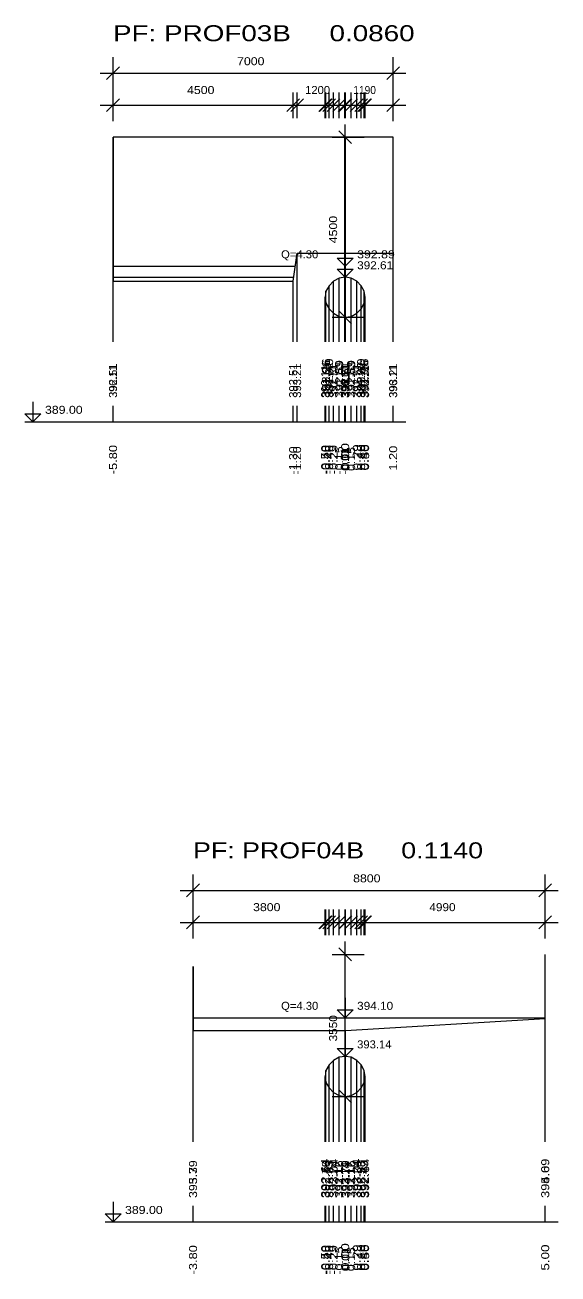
# Model space of a CAD drawing. Extents: x 7 to 442, y -393 to 441.
# Drawn here: x 414.04 to 427.36, y 175.67 to 206.88 of the extents above; entities that cross this region are included whole.
import ezdxf

# ---------------------------------------------------------------- set-up
doc = ezdxf.new("R2010")
doc.units = 0
doc.header["$LTSCALE"] = 0.08
doc.layers.add('7', color=7, linetype='Continuous', lineweight=13)

msp = doc.modelspace()

# ---------------------------------------------------------------- linework, layer by layer
at = {"layer": '7'}
for p, q in [((416.238, 204.479), (416.238, 206.079)), ((423.238, 204.479), (423.238, 206.079)), ((416.078, 205.519), (416.398, 205.839)), ((423.078, 205.519), (423.398, 205.839)), ((415.918, 205.679), (423.558, 205.679)), ((416.238, 204.559), (416.238, 205.199)), ((416.238, 204.559), (416.238, 205.199)), ((420.738, 204.559), (420.738, 205.199)), ((420.838, 204.559), (420.838, 205.199)), ((421.538, 204.559), (421.538, 205.199)), ((421.558, 204.559), (421.558, 205.199)), ((421.558, 204.559), (421.558, 205.199)), ((421.638, 204.559), (421.638, 205.199)), ((421.638, 204.559), (421.638, 205.199)), ((421.748, 204.559), (421.748, 205.199)), ((421.748, 204.559), (421.748, 205.199)), ((421.888, 204.559), (421.888, 205.199)), ((421.888, 204.559), (421.888, 205.199)), ((422.028, 204.559), (422.028, 205.199)), ((422.038, 204.559), (422.038, 205.199)), ((422.038, 204.559), (422.038, 205.199)), ((422.038, 204.559), (422.038, 205.199)), ((422.048, 204.559), (422.048, 205.199)), ((422.048, 204.559), (422.048, 205.199)), ((422.048, 204.559), (422.048, 205.199)), ((422.188, 204.559), (422.188, 205.199)), ((422.188, 204.559), (422.188, 205.199)), ((422.328, 204.559), (422.328, 205.199)), ((422.328, 204.559), (422.328, 205.199)), ((422.438, 204.559), (422.438, 205.199)), ((422.438, 204.559), (422.438, 205.199)), ((422.518, 204.559), (422.518, 205.199)), ((422.518, 204.559), (422.518, 205.199)), ((422.538, 204.559), (422.538, 205.199)), ((423.238, 204.559), (423.238, 205.199)), ((423.238, 204.559), (423.238, 205.199)), ((415.918, 204.879), (423.558, 204.879)), ((416.078, 204.719), (416.398, 205.039)), ((416.078, 204.719), (416.398, 205.039)), ((420.578, 204.719), (420.898, 205.039)), ((420.678, 204.719), (420.998, 205.039)), ((421.378, 204.719), (421.698, 205.039)), ((421.398, 204.719), (421.718, 205.039)), ((421.398, 204.719), (421.718, 205.039)), ((421.478, 204.719), (421.798, 205.039)), ((421.478, 204.719), (421.798, 205.039)), ((421.588, 204.719), (421.908, 205.039)), ((421.588, 204.719), (421.908, 205.039)), ((421.728, 204.719), (422.048, 205.039)), ((421.728, 204.719), (422.048, 205.039)), ((421.868, 204.719), (422.188, 205.039)), ((421.878, 204.719), (422.198, 205.039)), ((421.878, 204.719), (422.198, 205.039)), ((421.878, 204.719), (422.198, 205.039)), ((421.888, 204.719), (422.208, 205.039)), ((421.888, 204.719), (422.208, 205.039)), ((421.888, 204.719), (422.208, 205.039)), ((422.028, 204.719), (422.348, 205.039)), ((422.028, 204.719), (422.348, 205.039)), ((422.168, 204.719), (422.488, 205.039)), ((422.168, 204.719), (422.488, 205.039)), ((422.278, 204.719), (422.598, 205.039)), ((422.278, 204.719), (422.598, 205.039)), ((422.358, 204.719), (422.678, 205.039)), ((422.358, 204.719), (422.678, 205.039)), ((422.378, 204.719), (422.698, 205.039)), ((423.078, 204.719), (423.398, 205.039)), ((423.078, 204.719), (423.398, 205.039)), ((422.198, 203.919), (421.878, 204.239)), ((422.038, 199.419), (422.038, 204.399)), ((416.238, 198.966), (416.238, 204.079)), ((421.718, 204.079), (422.518, 204.079)), ((422.028, 198.966), (422.028, 204.079)), ((422.048, 198.966), (422.048, 204.079)), ((423.238, 198.966), (423.238, 204.079)), ((420.838, 198.966), (420.838, 201.179)), ((422.038, 198.966), (422.038, 201.179)), ((422.048, 198.966), (422.048, 201.179)), ((423.238, 198.966), (423.238, 201.179)), ((416.238, 200.853), (420.791, 200.853)), ((416.238, 200.579), (420.752, 200.579)), ((416.238, 198.966), (416.238, 200.479)), ((420.738, 198.966), (420.738, 200.479)), ((421.748, 198.966), (421.748, 200.479)), ((421.888, 198.966), (421.888, 200.559)), ((422.038, 198.966), (422.038, 200.579)), ((422.048, 198.966), (422.048, 200.579)), ((422.188, 198.966), (422.188, 200.559)), ((422.328, 198.966), (422.328, 200.479)), ((421.558, 198.966), (421.558, 200.229)), ((421.638, 198.966), (421.638, 200.369)), ((422.438, 198.966), (422.438, 200.369)), ((422.518, 198.966), (422.518, 200.229)), ((421.538, 198.966), (421.538, 200.079)), ((421.558, 198.966), (421.558, 199.929)), ((422.518, 198.966), (422.518, 199.929)), ((422.538, 198.966), (422.538, 200.079)), ((421.638, 198.966), (421.638, 199.789)), ((421.718, 199.579), (422.518, 199.579)), ((421.748, 198.966), (421.748, 199.679)), ((422.198, 199.419), (421.878, 199.739)), ((421.888, 198.966), (421.888, 199.599)), ((422.038, 198.966), (422.038, 199.579)), ((422.188, 198.966), (422.188, 199.599)), ((422.328, 198.966), (422.328, 199.679)), ((422.438, 198.966), (422.438, 199.789)), ((416.238, 196.966), (416.238, 197.366)), ((416.238, 196.966), (416.238, 197.366)), ((420.738, 196.966), (420.738, 197.366)), ((420.838, 196.966), (420.838, 197.366)), ((421.538, 196.966), (421.538, 197.366)), ((421.558, 196.966), (421.558, 197.366)), ((421.558, 196.966), (421.558, 197.366)), ((421.638, 196.966), (421.638, 197.366)), ((421.638, 196.966), (421.638, 197.366)), ((421.748, 196.966), (421.748, 197.366)), ((421.748, 196.966), (421.748, 197.366)), ((421.888, 196.966), (421.888, 197.366)), ((421.888, 196.966), (421.888, 197.366)), ((422.028, 196.966), (422.028, 197.366)), ((422.038, 196.966), (422.038, 197.366)), ((422.038, 196.966), (422.038, 197.366)), ((422.038, 196.966), (422.038, 197.366)), ((422.048, 196.966), (422.048, 197.366)), ((422.048, 196.966), (422.048, 197.366)), ((422.048, 196.966), (422.048, 197.366)), ((422.188, 196.966), (422.188, 197.366)), ((422.188, 196.966), (422.188, 197.366)), ((422.328, 196.966), (422.328, 197.366)), ((422.328, 196.966), (422.328, 197.366)), ((422.438, 196.966), (422.438, 197.366)), ((422.438, 196.966), (422.438, 197.366)), ((422.518, 196.966), (422.518, 197.366)), ((422.518, 196.966), (422.518, 197.366)), ((422.538, 196.966), (422.538, 197.366)), ((423.238, 196.966), (423.238, 197.366)), ((423.238, 196.966), (423.238, 197.366)), ((414.038, 196.966), (423.558, 196.966)), ((418.238, 184.055), (418.238, 185.655)), ((427.038, 184.055), (427.038, 185.655)), ((417.918, 185.255), (427.358, 185.255)), ((418.078, 185.095), (418.398, 185.415)), ((426.878, 185.095), (427.198, 185.415)), ((418.078, 184.295), (418.398, 184.615)), ((418.078, 184.295), (418.398, 184.615)), ((418.238, 184.135), (418.238, 184.775)), ((418.238, 184.135), (418.238, 184.775)), ((421.378, 184.295), (421.698, 184.615)), ((421.398, 184.295), (421.718, 184.615)), ((421.398, 184.295), (421.718, 184.615)), ((421.478, 184.295), (421.798, 184.615)), ((421.478, 184.295), (421.798, 184.615)), ((421.538, 184.135), (421.538, 184.775)), ((421.558, 184.135), (421.558, 184.775)), ((421.558, 184.135), (421.558, 184.775)), ((421.588, 184.295), (421.908, 184.615)), ((421.588, 184.295), (421.908, 184.615)), ((421.638, 184.135), (421.638, 184.775)), ((421.638, 184.135), (421.638, 184.775)), ((421.728, 184.295), (422.048, 184.615)), ((421.728, 184.295), (422.048, 184.615)), ((421.748, 184.135), (421.748, 184.775)), ((421.748, 184.135), (421.748, 184.775)), ((421.878, 184.295), (422.198, 184.615)), ((421.878, 184.295), (422.198, 184.615)), ((421.878, 184.295), (422.198, 184.615)), ((421.888, 184.135), (421.888, 184.775)), ((421.888, 184.135), (421.888, 184.775)), ((421.888, 184.295), (422.208, 184.615)), ((421.888, 184.295), (422.208, 184.615)), ((422.028, 184.295), (422.348, 184.615)), ((422.028, 184.295), (422.348, 184.615)), ((422.038, 184.135), (422.038, 184.775)), ((422.038, 184.135), (422.038, 184.775)), ((422.038, 184.135), (422.038, 184.775)), ((422.048, 184.135), (422.048, 184.775)), ((422.048, 184.135), (422.048, 184.775)), ((422.168, 184.295), (422.488, 184.615)), ((422.168, 184.295), (422.488, 184.615)), ((422.188, 184.135), (422.188, 184.775)), ((422.188, 184.135), (422.188, 184.775)), ((422.278, 184.295), (422.598, 184.615)), ((422.278, 184.295), (422.598, 184.615)), ((422.328, 184.135), (422.328, 184.775)), ((422.328, 184.135), (422.328, 184.775)), ((422.358, 184.295), (422.678, 184.615)), ((422.358, 184.295), (422.678, 184.615)), ((422.378, 184.295), (422.698, 184.615)), ((422.438, 184.135), (422.438, 184.775)), ((422.438, 184.135), (422.438, 184.775)), ((422.518, 184.135), (422.518, 184.775)), ((422.518, 184.135), (422.518, 184.775)), ((422.538, 184.135), (422.538, 184.775)), ((426.878, 184.295), (427.198, 184.615)), ((426.878, 184.295), (427.198, 184.615)), ((427.038, 184.135), (427.038, 184.775)), ((427.038, 184.135), (427.038, 184.775)), ((417.918, 184.455), (427.358, 184.455)), ((422.038, 179.945), (422.038, 183.975)), ((421.718, 183.655), (422.518, 183.655)), ((422.198, 183.495), (421.878, 183.815)), ((427.038, 178.966), (427.038, 183.655)), ((418.238, 178.966), (418.238, 183.355)), ((418.238, 182.069), (427.038, 182.069)), ((427.038, 178.966), (427.038, 182.055)), ((418.238, 178.966), (418.238, 181.755)), ((422.038, 178.966), (422.038, 181.755)), ((422.048, 178.966), (422.048, 181.755)), ((421.888, 178.966), (421.888, 181.085)), ((422.038, 178.966), (422.038, 181.105)), ((422.038, 181.105), (422.048, 181.105)), ((422.048, 178.966), (422.048, 181.105)), ((422.188, 178.966), (422.188, 181.085)), ((421.638, 178.966), (421.638, 180.895)), ((421.748, 178.966), (421.748, 181.005)), ((422.328, 178.966), (422.328, 181.005)), ((422.438, 178.966), (422.438, 180.895)), ((421.538, 178.966), (421.538, 180.605)), ((421.558, 178.966), (421.558, 180.755)), ((421.558, 178.966), (421.558, 180.455)), ((422.518, 178.966), (422.518, 180.755)), ((422.518, 178.966), (422.518, 180.455)), ((422.538, 178.966), (422.538, 180.605)), ((421.638, 178.966), (421.638, 180.315)), ((421.748, 178.966), (421.748, 180.205)), ((422.198, 179.945), (421.878, 180.265)), ((422.328, 178.966), (422.328, 180.205)), ((422.438, 178.966), (422.438, 180.315)), ((421.718, 180.105), (422.518, 180.105)), ((421.888, 178.966), (421.888, 180.125)), ((422.038, 178.966), (422.038, 180.105)), ((422.188, 178.966), (422.188, 180.125)), ((418.238, 176.966), (418.238, 177.366)), ((418.238, 176.966), (418.238, 177.366)), ((421.538, 176.966), (421.538, 177.366)), ((421.558, 176.966), (421.558, 177.366)), ((421.558, 176.966), (421.558, 177.366)), ((421.638, 176.966), (421.638, 177.366)), ((421.638, 176.966), (421.638, 177.366)), ((421.748, 176.966), (421.748, 177.366)), ((421.748, 176.966), (421.748, 177.366)), ((421.888, 176.966), (421.888, 177.366)), ((421.888, 176.966), (421.888, 177.366)), ((422.038, 176.966), (422.038, 177.366)), ((422.038, 176.966), (422.038, 177.366)), ((422.038, 176.966), (422.038, 177.366)), ((422.048, 176.966), (422.048, 177.366)), ((422.048, 176.966), (422.048, 177.366)), ((422.188, 176.966), (422.188, 177.366)), ((422.188, 176.966), (422.188, 177.366)), ((422.328, 176.966), (422.328, 177.366)), ((422.328, 176.966), (422.328, 177.366)), ((422.438, 176.966), (422.438, 177.366)), ((422.438, 176.966), (422.438, 177.366)), ((422.518, 176.966), (422.518, 177.366)), ((422.518, 176.966), (422.518, 177.366)), ((422.538, 176.966), (422.538, 177.366)), ((427.038, 176.966), (427.038, 177.366)), ((427.038, 176.966), (427.038, 177.366)), ((416.038, 176.966), (427.358, 176.966))]:
    msp.add_line(p, q, dxfattribs=at)
for points in [[(422.028, 204.079), (416.238, 204.079), (416.238, 200.479), (420.738, 200.479), (420.838, 201.179), (422.038, 201.179), (422.038, 200.579), (421.888, 200.559), (421.748, 200.479), (421.638, 200.369), (421.558, 200.229), (421.538, 200.079), (421.558, 199.929), (421.638, 199.789), (421.748, 199.679), (421.888, 199.599), (422.038, 199.579), (422.188, 199.599), (422.328, 199.679), (422.438, 199.789), (422.518, 199.929), (422.538, 200.079), (422.518, 200.229), (422.438, 200.369), (422.328, 200.479), (422.188, 200.559), (422.048, 200.579), (422.048, 201.179), (423.238, 201.179), (423.238, 204.079), (422.048, 204.079)], [(422.038, 201.353), (422.038, 200.853), (421.838, 201.053), (422.238, 201.053), (422.038, 200.853), (422.048, 200.853)], [(422.038, 201.079), (422.038, 200.579), (421.838, 200.779), (422.238, 200.779), (422.038, 200.579), (422.048, 200.579)], [(414.238, 197.466), (414.238, 196.966), (414.038, 197.166), (414.438, 197.166), (414.238, 196.966)], [(418.238, 183.355), (418.238, 181.755), (422.038, 181.755), (422.038, 181.105), (421.888, 181.085), (421.748, 181.005), (421.638, 180.895), (421.558, 180.755), (421.538, 180.605), (421.558, 180.455), (421.638, 180.315), (421.748, 180.205), (421.888, 180.125), (422.038, 180.105), (422.188, 180.125), (422.328, 180.205), (422.438, 180.315), (422.518, 180.455), (422.538, 180.605), (422.518, 180.755), (422.438, 180.895), (422.328, 181.005), (422.188, 181.085), (422.048, 181.105), (422.048, 181.755), (427.038, 182.055), (427.038, 183.655)], [(422.038, 182.569), (422.038, 182.069), (421.838, 182.269), (422.238, 182.269), (422.038, 182.069)], [(422.038, 181.605), (422.038, 181.105), (421.838, 181.305), (422.238, 181.305), (422.038, 181.105)], [(416.238, 177.466), (416.238, 176.966), (416.038, 177.166), (416.438, 177.166), (416.238, 176.966)]]:
    msp.add_lwpolyline(points, dxfattribs=at)

# ---------------------------------------------------------------- texts
for s, height, width, p in [('PF: PROF03B     0.0860', 0.4, 1.3, (416.238, 206.479)), ('7000', 0.2, 1.15, (419.338, 205.879)), ('4500', 0.2, 1.15, (418.088, 205.159)), ('1200', 0.2, 1.05, (421.038, 205.159)), ('1190', 0.2, 0.95, (422.243, 205.159)), ('Q=4.30', 0.2, 1.05, (420.438, 201.053)), ('392.89', 0.2, 1.15, (422.338, 201.053)), ('392.61', 0.2, 1.1, (422.338, 200.779)), ('389.00', 0.2, 1.15, (414.538, 197.166)), ('PF: PROF04B     0.1140', 0.4, 1.25, (418.238, 186.055)), ('8800', 0.2, 1.15, (422.238, 185.455)), ('3800', 0.2, 1.15, (419.738, 184.735)), ('4990', 0.2, 1.1, (424.143, 184.735)), ('Q=4.30', 0.2, 1.05, (420.438, 182.269)), ('394.10', 0.2, 1.1, (422.338, 182.269)), ('393.14', 0.2, 1.05, (422.338, 181.305)), ('389.00', 0.2, 1.15, (416.538, 177.166))]:
    msp.add_text(s, height=height, dxfattribs=dict(at, width=width)).set_placement(p)
for s, width, p in [('4500', 1.15, (421.838, 201.429)), ('392.51 ', 1.05, (416.338, 197.566)), ('392.51 ', 1.05, (420.838, 197.566)), ('393.21 ', 1.05, (420.938, 197.566)), ('392.26 ', 1.2, (421.658, 197.566)), ('391.96 ', 1.15, (421.658, 197.566)), ('392.40 ', 1.2, (421.738, 197.566)), ('391.82 ', 1.1, (421.738, 197.566)), ('392.51 ', 1.05, (421.848, 197.566)), ('392.59 ', 1.15, (421.988, 197.566)), ('391.63 ', 1.1, (421.988, 197.566)), ('392.61 ', 1.1, (422.138, 197.566)), ('393.21 ', 1.05, (422.138, 197.566)), ('392.61 ', 1.1, (422.148, 197.566)), ('393.21 ', 1.05, (422.148, 197.566)), ('392.59 ', 1.15, (422.288, 197.566)), ('391.63 ', 1.1, (422.288, 197.566)), ('392.51 ', 1.05, (422.428, 197.566)), ('392.40 ', 1.2, (422.538, 197.566)), ('391.82 ', 1.1, (422.538, 197.566)), ('392.26 ', 1.2, (422.618, 197.566)), ('391.96 ', 1.15, (422.618, 197.566)), ('393.21 ', 1.05, (423.338, 197.566)), (' -5.80 ', 1.2, (416.338, 195.566)), (' -5.80 ', 1.2, (416.338, 195.566)), (' -0.50 ', 1.2, (421.638, 195.566)), (' -0.40 ', 1.2, (421.738, 195.566)), (' -0.40 ', 1.2, (421.738, 195.566)), ('  0.00 ', 1.3, (422.138, 195.566)), ('  0.00 ', 1.3, (422.138, 195.566)), ('  0.00 ', 1.3, (422.138, 195.566)), ('  0.29 ', 1.25, (422.428, 195.566)), ('  0.29 ', 1.25, (422.428, 195.566)), ('  0.40 ', 1.25, (422.538, 195.566)), ('  0.40 ', 1.25, (422.538, 195.566)), ('  0.48 ', 1.25, (422.618, 195.566)), ('  0.48 ', 1.25, (422.618, 195.566)), ('  0.50 ', 1.25, (422.638, 195.566)), (' -1.30 ', 1.15, (420.838, 195.566)), (' -1.20 ', 1.15, (420.938, 195.566)), (' -0.48 ', 1.2, (421.658, 195.566)), (' -0.48 ', 1.2, (421.658, 195.566)), (' -0.29 ', 1.2, (421.848, 195.566)), (' -0.29 ', 1.2, (421.848, 195.566)), (' -0.15 ', 1.15, (421.988, 195.566)), (' -0.15 ', 1.15, (421.988, 195.566)), (' -0.01 ', 1.1, (422.128, 195.566)), ('  0.01 ', 1.15, (422.148, 195.566)), ('  0.01 ', 1.15, (422.148, 195.566)), ('  0.01 ', 1.15, (422.148, 195.566)), ('  0.15 ', 1.15, (422.288, 195.566)), ('  0.15 ', 1.15, (422.288, 195.566)), ('  1.20 ', 1.2, (423.338, 195.566)), ('  1.20 ', 1.2, (423.338, 195.566)), ('3550', 1.1, (421.838, 181.48)), ('395.39 ', 1.15, (418.338, 177.566)), ('393.79 ', 1.15, (418.338, 177.566)), ('392.64 ', 1.2, (421.638, 177.566)), ('392.79 ', 1.15, (421.658, 177.566)), ('392.49 ', 1.15, (421.658, 177.566)), ('392.35 ', 1.15, (421.738, 177.566)), ('392.93 ', 1.15, (421.738, 177.566)), ('393.04 ', 1.2, (421.848, 177.566)), ('392.24 ', 1.15, (421.848, 177.566)), ('392.16 ', 1.15, (421.988, 177.566)), ('393.12 ', 1.1, (421.988, 177.566)), ('393.79 ', 1.15, (422.138, 177.566)), ('393.14 ', 1.1, (422.138, 177.566)), ('392.14 ', 1.1, (422.138, 177.566)), ('393.79 ', 1.15, (422.148, 177.566)), ('393.14 ', 1.1, (422.148, 177.566)), ('392.16 ', 1.15, (422.288, 177.566)), ('393.12 ', 1.1, (422.288, 177.566)), ('393.04 ', 1.2, (422.428, 177.566)), ('392.24 ', 1.15, (422.428, 177.566)), ('392.35 ', 1.15, (422.538, 177.566)), ('392.93 ', 1.15, (422.538, 177.566)), ('392.49 ', 1.15, (422.618, 177.566)), ('392.79 ', 1.15, (422.618, 177.566)), ('392.64 ', 1.2, (422.638, 177.566)), ('394.09 ', 1.2, (427.138, 177.566)), ('395.69 ', 1.2, (427.138, 177.566)), ('  0.00 ', 1.3, (422.138, 175.566)), ('  0.00 ', 1.3, (422.138, 175.566)), ('  0.00 ', 1.3, (422.138, 175.566)), (' -3.80 ', 1.2, (418.338, 175.566)), (' -3.80 ', 1.2, (418.338, 175.566)), (' -0.50 ', 1.2, (421.638, 175.566)), (' -0.48 ', 1.2, (421.658, 175.566)), (' -0.48 ', 1.2, (421.658, 175.566)), (' -0.40 ', 1.2, (421.738, 175.566)), (' -0.40 ', 1.2, (421.738, 175.566)), (' -0.29 ', 1.2, (421.848, 175.566)), (' -0.29 ', 1.2, (421.848, 175.566)), (' -0.15 ', 1.15, (421.988, 175.566)), (' -0.15 ', 1.15, (421.988, 175.566)), ('  0.01 ', 1.15, (422.148, 175.566)), ('  0.01 ', 1.15, (422.148, 175.566)), ('  0.15 ', 1.15, (422.288, 175.566)), ('  0.15 ', 1.15, (422.288, 175.566)), ('  0.29 ', 1.25, (422.428, 175.566)), ('  0.29 ', 1.25, (422.428, 175.566)), ('  0.40 ', 1.25, (422.538, 175.566)), ('  0.40 ', 1.25, (422.538, 175.566)), ('  0.48 ', 1.25, (422.618, 175.566)), ('  0.48 ', 1.25, (422.618, 175.566)), ('  0.50 ', 1.25, (422.638, 175.566)), ('  5.00 ', 1.25, (427.138, 175.566)), ('  5.00 ', 1.25, (427.138, 175.566))]:
    msp.add_text(s, height=0.2, rotation=90, dxfattribs=dict(at, width=width)).set_placement(p)
for s, p in [('396.11 ', (416.338, 197.566)), ('392.11 ', (421.638, 197.566)), ('391.71 ', (421.848, 197.566)), ('396.11 ', (422.128, 197.566)), ('391.61 ', (422.138, 197.566)), ('396.11 ', (422.148, 197.566)), ('391.71 ', (422.428, 197.566)), ('392.11 ', (422.638, 197.566)), ('396.11 ', (423.338, 197.566))]:
    msp.add_text(s, height=0.2, rotation=90, dxfattribs=at).set_placement(p)

doc.saveas('drawing.dxf')
